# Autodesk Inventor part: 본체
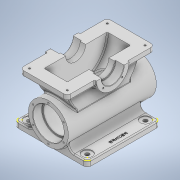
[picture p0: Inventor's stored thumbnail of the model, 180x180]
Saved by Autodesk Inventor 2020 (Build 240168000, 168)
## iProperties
Created: 2023-07
Part Number: 본체
Material: 일반
Document SubType Name: Modeling
Designer: home
Density: 1 g/cm^3
Appearance: 기본값
Mass: 2162.34 g
Surface Area: 2899.12 cm^2
Volume: 2162.34 cm^3
Author: home
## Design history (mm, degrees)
sketch "스케치1"
  geometry: C1 r 55 at (0, 0); 1 further point
  constraints: 1 centre point, 1 coincident
  dimensions: "d0" = 110 diameter of C1
extrude "돌출1" new body sketch "스케치1" stored distance "d1" = 242; taper "d2" = 0 deg
node "작업 평면1"
sketch "스케치2"
  geometry: L1 (55, 121)-(-55, 121) reference; L2 (55, 14)-(-55, 14); L3 (0, 14)-(0, 121); L4 (65, 134)-(-65, 134); L5 (-65, 134)-(-65, -106); L6 (-65, -106)-(65, -106); L7 (65, -106)-(65, 134); L8 (65, 134)-(-65, -106); L9 (-65, 134)-(65, -106); 1 further point
  constraints: 16 end point, 4 midpoint, 3 parallel, 1 horizontal, 1 perpendicular
  dimensions: "d4" = 107 distance between parallel lines of L1 L2; "d5" = 107 distance of L3.start L3.end; "d6" = 130 distance of L6.end L5.end; "d7" = 240 distance of L6.end L4.start
extrude "돌출2" join sketch "스케치2" distance "d8" = 15; taper "d9" = 0 deg
node "작업 평면2"
sketch "스케치3"
  geometry: L1 (0, 0)-(0, -15) reference; L2 (13, -50)-(13, -160) reference; L3 (13, -50)-(13, 0); L4 (120, 0)-(120, -50); L5 (120, -50)-(120, -160); L6 (240, 0)-(0, 0) reference; C1 r 100 at (120, 0); 3 further points
  constraints: 6 end point, 1 centre point, 1 coincident, 1 vertical, 1 other
  dimensions: "d11" = 107 distance between parallel lines of L3 L4; "d12" = 200 diameter of C1
extrude "돌출3" join sketch "스케치3" stored distance "d13" = 90; taper "d14" = 0 deg
sketch "스케치4"
  geometry: L1 (240, 0)-(0, 0) reference; C1 r 45 at (120, 0); 3 further points
  constraints: 1 centre point, 1 midpoint
  dimensions: "d15" = 90 diameter of C1
extrude "돌출4" join sketch "스케치4" stored distance "d16" = 140; taper "d17" = 0 deg
sketch "스케치5"
  geometry: C1 r 31 at (120, 0); A1 r 45 centre (120, 0) between (75, 0) and (165, 0) reference; 1 further point
  constraints: 1 centre point, 1 coincident
  dimensions: "d18" = 62 diameter of C1
extrude "돌출5" cut sketch "스케치5" distance "d19" = 23; taper "d20" = 0 deg
sketch "스케치7"
  geometry: L1 (75, 0)-(165, 0) reference; C1 r 87 at (120, 0); 1 further point
  constraints: 1 centre point, 1 midpoint
  dimensions: "d21" = 174 diameter of C1
extrude "돌출6" cut sketch "스케치7" stored distance "d22" = 64; taper "d23" = 0 deg
sketch "스케치8"
  geometry: L1 (89, 0)-(151, 0) reference; C1 r 27.5 at (120, 0); A1 r 31 centre (120, 0) between (89, 0) and (151, 0) reference; 1 further point
  constraints: 1 centre point, 1 coincident
  dimensions: "d24" = 55 diameter of C1
extrude "돌출7" cut sketch "스케치8" stored distance "d25" = 64; taper "d26" = 0 deg
sketch "스케치9"
  geometry: 1 further point
sketch "스케치10"
  geometry: L1 (-55, -14)-(55, -14) reference; L2 (-55, 93)-(55, 93); L3 (0, 0)-(0, 93); L4 (52, 0)-(52, 93); L5 (-52, 0)-(-52, 93); L6 (-55, -121)-(55, -121) reference; 4 further points
  constraints: 8 end point, 3 parallel, 2 coincident, 2 symmetric about line, 1 midpoint
  dimensions: "d27" = 107 distance between parallel lines of L1 L2; "d28" = 93 distance of L3.start L3.end; "d29" = 52 distance between parallel lines of L3 L4; "d30" = 52 distance between parallel lines of L3 L5
hole "구멍1" sketch "스케치10" at (-52, -121), (52, -121), (52, 93), (-52, 93) diameter "d31" = 4.917; stored, may be unused: countersink angle "d35" = 90 deg, drill point angle "d37" = 0 deg; dims "d32" = 12, "d33" = 4, "d34" = 2, "d36" = 17.1
sketch "스케치11"
  geometry: L1 (120, 0)-(120, -37); L2 (120, 0)-(93.837, -26.163); L3 (120, 0)-(146.163, -26.163); A1 r 45 centre (120, 0) between (75, 0) and (165, 0) reference; A2 r 37 centre (120, 0) between (120, -37) and (93.837, -26.163); 3 further points
  constraints: 6 end point, 3 coincident, 3 point on circle, 1 centre point, 1 vertical
  dimensions: "d38" = 74 diameter of A2; "d39" = 45 deg angle of L2 L1; "d40" = 45 deg angle of L1 L3
hole "구멍2" sketch "스케치11" at (93.837, -26.163), (146.163, -26.163) diameter "d41" = 4.134; stored, may be unused: countersink angle "d45" = 90 deg, drill point angle "d47" = 118 deg; dims "d42" = 10, "d43" = 4, "d44" = 2, "d46" = 12
sketch "스케치12"
  geometry: L1 (55, 121)-(-55, 121) reference; L2 (0, 121)-(0, -121); L3 (-55, -121)-(55, -121) reference; L4 (42.5, 121)-(42.5, 96); L5 (42.5, 96)-(38.5, 96); L6 (38.5, 96)-(38.5, -96); L7 (38.5, -96)-(42.5, -96); L8 (42.5, -96)-(42.5, -121); L9 (42.5, 121)-(0, 121); L10 (42.5, -121)-(0, -121); 1 further point
  constraints: 16 end point, 4 perpendicular, 4 point on line, 2 midpoint, 1 collinear, 1 horizontal
  dimensions: "d48" = 85 diameter of L4 L2; "d49" = 25 distance of L4.start L4.end; "d50" = 25 distance of L7.end L8.end; "d51" = 77 diameter of L6 L2
revolve "회전1" sketch "스케치12" stored, may be unused: angle "d52" = 90 deg
sketch "스케치13"
  geometry: L1 (0, 48.5)-(0, -48.5); L2 (-48.5, 0)-(48.5, 0); L3 (0, 0)-(42.002, 24.25); L4 (0, 0)-(-42.002, 24.25); L5 (0, 0)-(-42.002, -24.25); L6 (0, 0)-(42.002, -24.25); C1 r 42.5 at (0, 0) reference; A1 r 48.5 centre (0, 0) between (0, 48.5) and (0, -48.5); 7 further points
  constraints: 12 end point, 7 coincident, 6 point on circle, 2 symmetric about line, 1 centre point, 1 horizontal, 1 vertical
  dimensions: "d53" = 97 diameter of A1; "d54" = 97 distance of L1.start L1.end; "d55" = 97 distance of L2.start L2.end; "d56" = 60 deg angle of L1 L4; "d57" = 60 deg angle of L1 L3
hole "구멍3" sketch "스케치13" at (-42.002, 24.25), (0, 48.5), (42.002, 24.25), (42.002, -24.25), (0, -48.5), (-42.002, -24.25) diameter "d58" = 4.134; stored, may be unused: countersink angle "d62" = 90 deg, drill point angle "d64" = 118 deg; dims "d59" = 10, "d60" = 4, "d61" = 2, "d63" = 12
node "작업 평면3"
sketch "스케치14"
  geometry: L1 (0, 243.4)-(0, -256.4) reference; L2 (-55, -121)-(55, -121) reference; L3 (-100, -114)-(100, -114); L4 (-100, 86)-(100, 86); L5 (-100, 172)-(-100, -185); L6 (100, 172)-(100, -185); 1 further point
  constraints: 8 end point, 4 parallel, 4 point on line
  dimensions: "d66" = 7 distance between parallel lines of L2 L3; "d67" = 200 distance between parallel lines of L3 L4; "d68" = 100 distance between parallel lines of L1 L5; "d69" = 100 distance between parallel lines of L1 L6
extrude "돌출8" join sketch "스케치14" distance "d70" = 15; taper "d71" = 0 deg
sketch "스케치15"
  geometry: L1 (-55, -121)-(55, -121) reference; L2 (-55, -14)-(100, -14); L3 (100, -114)-(100, 86) reference; L4 (-55, -94)-(100, -94); L5 (-55, 66)-(100, 66); L6 (0, -94)-(0, 66); L7 (80, -94)-(80, 66); L8 (-80, -94)-(-80, 66); C1 r 14 at (80, 66); C2 r 14 at (80, -94); 1 further point
  constraints: 12 end point, 5 parallel, 3 point on line, 2 centre point, 2 coincident, 1 midpoint, 1 perpendicular
  dimensions: "d72" = 107 distance between parallel lines of L1 L2; "d73" = 80 distance between parallel lines of L2 L4; "d74" = 80 distance between parallel lines of L2 L5; "d76" = 80 distance between parallel lines of L6 L7; "d77" = 80 distance between parallel lines of L6 L8; "d78" = 28 diameter of C1; "d79" = 28 diameter of C2; "d80" = 80 distance from line of L2 L7.end; "d81" = 80 distance from line of L2 C2.centre
fillet "모깎기1" dims "d75" = 10
sketch "스케치16"
  geometry: A1 r 10 centre (90, 76) between (100, 76) and (90, 86) reference; A2 r 10 centre (90, -104) between (90, -114) and (100, -104) reference; A3 r 10 centre (-90, -104) between (-100, -104) and (-90, -114) reference; A4 r 10 centre (-90, 76) between (-90, 86) and (-100, 76) reference; 1 further point
extrude "돌출9" cut sketch "스케치15" distance "d82" = 2; taper "d83" = 0 deg
sketch "스케치17"
  geometry: C1 r 14 at (0, 0) reference; C2 r 5.5 at (0, 0); 1 further point
  constraints: 1 centre point, 1 coincident
  dimensions: "d84" = 11 diameter of C2
extrude "돌출10" cut sketch "스케치17" extent not by distance; stored distance "d85" = 0; taper "d86" = 0 deg
sketch "스케치18"
  geometry: C1 r 14 at (0, 0) reference; C2 r 5.5 at (0, 0); 1 further point
  constraints: 1 centre point, 1 coincident
  dimensions: "d87" = 11 diameter of C2
extrude "돌출11" cut sketch "스케치18" extent not by distance; stored distance "d88" = 0; taper "d89" = 0 deg
node "작업 평면4"
fillet "모깎기5" dims "d94" = 15
fillet "모깎기6" dims "d95" = 3
fillet "모깎기7" dims "d96" = 3
fillet "모깎기8" dims "d97" = 3
fillet "모깎기9" dims "d98" = 3
fillet "모깎기10" dims "d99" = 3
fillet "모깎기11" dims "d100" = 3
fillet "모깎기15" dims "d104" = 10
fillet "모깎기16" dims "d105" = 3
fillet "모깎기17" dims "d106" = 3
fillet "모깎기18" dims "d107" = 3
chamfer "모따기1" distance "d108" = 1; stored, may be unused: second distance "d109" = 2, angle "d110" = 45 deg
fillet "모깎기19" dims "d111" = 1
chamfer "모따기2" distance "d112" = 1; stored, may be unused: second distance "d113" = 2, angle "d114" = 45 deg
fillet "모깎기20" dims "d115" = 1.1
fillet "모깎기21" dims "d116" = 3
fillet "모깎기22" dims "d117" = 3
fillet "모깎기23" dims "d118" = 3
sketch "스케치19"
  geometry: L1 (100, -104)-(100, 76) reference; L2 (85, -104)-(85, 76); L3 (70, -59)-(70, 31) reference; L4 (69, 17)-(69, -45) reference; L5 (-55, -121)-(55, -121) reference; L6 (-55, -14)-(85, -14); 3 further points
  constraints: 4 end point, 2 midpoint, 2 parallel, 1 coincident, 1 other
  dimensions: "d119" = 15 distance between parallel lines of L1 L2; "d120" = 107 distance between parallel lines of L5 L6
feature "엠보싱1" sketch "스케치19" dims "d10" = -65, "d121" = 0.5, "d122" = 0
fillet "모깎기24" dims "d123" = 3
node "솔리드1"
mirror "미러1"
mirror "미러2"
mirror "미러3"
mirror "미러4"
mirror "미러5"
mirror "미러6"
node "투영된 루프1"
feature "A9D066F2-1C7D-4E18-AEED-F7BC21143FA4" dims "d41" = 4.134, "d42" = 10, "d43" = 4, "d44" = 2, "d45" = 90 deg, "d46" = 12, "d47" = 118 deg
other parameters: "d3" = 105, "d65" = -165
